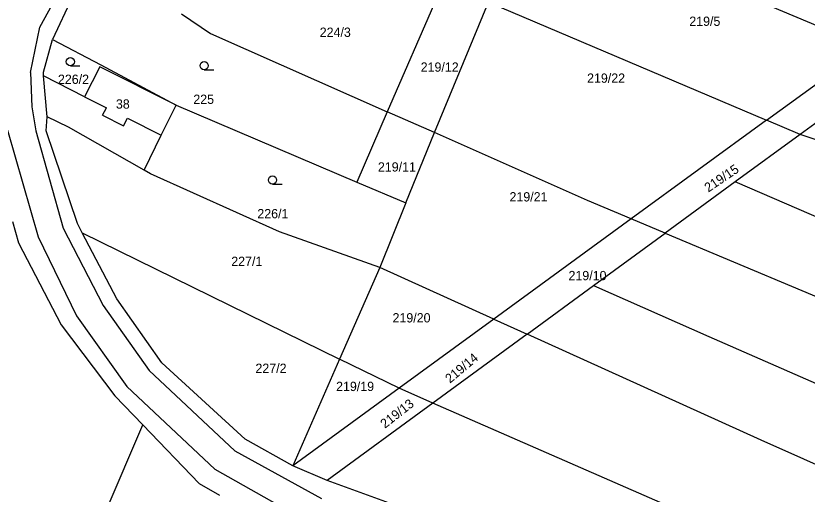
# Model space of a CAD drawing. Extents: x -744566 to -741843, y -1128407 to -1126744.
# Drawn here: x -743048.6 to -742903.8, y -1127789.3 to -1127701.7 of the extents above; entities that cross this region are included whole.
import ezdxf

# ---------------------------------------------------------------- set-up
doc = ezdxf.new("R2010")
doc.units = 0
for name, color, linetype in [('Hranice parcel', 7, 'Continuous'), ('Parcelní čísla', 7, 'Continuous'), ('Vnitřní kresba', 7, 'Continuous'), ('Značky kultur', 7, 'Continuous')]:
    doc.layers.add(name, color=color, linetype=linetype)

msp = doc.modelspace()

# ---------------------------------------------------------------- linework, layer by layer
at = {"layer": 'Hranice parcel'}
for p, q in [((-743035.1, -1127691.53), (-743041.92, -1127706.05)), ((-742970.18, -1127695.1), (-742980.63, -1127719.3)), ((-742972.01, -1127723.11), (-742962.09, -1127699.23)), ((-742962.09, -1127699.23), (-742911.19, -1127720.85)), ((-742911.19, -1127720.85), (-742892.82, -1127707.45)), ((-742886.72, -1127710.02), (-742905.07, -1127723.45)), ((-743042.89, -1127720.23), (-743043.57, -1127712.76)), ((-743019.3, -1127718.08), (-742986.19, -1127732.18)), ((-742980.63, -1127719.3), (-742986.19, -1127732.18)), ((-742972.01, -1127723.11), (-742980.63, -1127719.3)), ((-742911.19, -1127720.85), (-742935.96, -1127738.92)), ((-742905.07, -1127723.45), (-742911.19, -1127720.85)), ((-742977.22, -1127736), (-742972.01, -1127723.11)), ((-742905.07, -1127723.45), (-742916.95, -1127732.14)), ((-742986.19, -1127732.18), (-742977.22, -1127736)), ((-742916.95, -1127732.14), (-742929.76, -1127741.52)), ((-742977.22, -1127736), (-742982, -1127747.83)), ((-742935.96, -1127738.92), (-742961.12, -1127757.28)), ((-742929.76, -1127741.52), (-742935.96, -1127738.92)), ((-743036.47, -1127741.45), (-742989.35, -1127764.58)), ((-742942.9, -1127751.14), (-742929.76, -1127741.52)), ((-742982, -1127747.83), (-742989.35, -1127764.58)), ((-742961.12, -1127757.28), (-742982, -1127747.83)), ((-742955.04, -1127760.03), (-742942.9, -1127751.14)), ((-742961.12, -1127757.28), (-742978.46, -1127769.93)), ((-742961.12, -1127757.28), (-742955.04, -1127760.03)), ((-742955.04, -1127760.03), (-742972.27, -1127772.64)), ((-742989.35, -1127764.58), (-742997.92, -1127784.13)), ((-742978.46, -1127769.93), (-742989.35, -1127764.58)), ((-742978.46, -1127769.93), (-742997.92, -1127784.13)), ((-742972.27, -1127772.64), (-742978.46, -1127769.93)), ((-742972.27, -1127772.64), (-742991.64, -1127786.82)), ((-742833.19, -1127833.4), (-742972.27, -1127772.64)), ((-742991.64, -1127786.82), (-742997.92, -1127784.13))]:
    msp.add_line(p, q, dxfattribs=at)
for points in [[(-742892.82, -1127707.45), (-742959.07, -1127679.57), (-742986.2, -1127666.67), (-743003.07, -1127657.38)], [(-743018.27, -1127701.4), (-743013, -1127704.97), (-742980.63, -1127719.3)], [(-743043.57, -1127712.76), (-743043.55, -1127712.08), (-743041.92, -1127706.05)], [(-743041.92, -1127706.05), (-743033.05, -1127710.69), (-743019.3, -1127718.08)], [(-743019.3, -1127718.08), (-743033.26, -1127711.09), (-743036.05, -1127716.56), (-743043.57, -1127712.76)], [(-743025.14, -1127730.02), (-743022, -1127723.61), (-743019.3, -1127718.08)], [(-743036.47, -1127741.45), (-743037.36, -1127739.74), (-743043.04, -1127722.81), (-743042.89, -1127720.23)], [(-743025.14, -1127730.02), (-743039.01, -1127722.1), (-743042.89, -1127720.23)], [(-742935.96, -1127738.92), (-742943.98, -1127735.55), (-742972.01, -1127723.11)], [(-742697.57, -1127810.08), (-742723.74, -1127797.75), (-742779.52, -1127774.85), (-742849.36, -1127744.61), (-742849.6, -1127747), (-742896.29, -1127726.42), (-742905.07, -1127723.45)], [(-742982, -1127747.83), (-743000.34, -1127741.31), (-743023.98, -1127730.68), (-743025.14, -1127730.02)], [(-742705.33, -1127822.31), (-742752.11, -1127800.85), (-742855.88, -1127756.96), (-742856.57, -1127758.28), (-742916.95, -1127732.14)], [(-743049.21, -1127739.41), (-743048.14, -1127743.3), (-743040.35, -1127758.3), (-743030.5, -1127771.33), (-743025.38, -1127776.65)], [(-742997.92, -1127784.13), (-743006.65, -1127779.24), (-743021.89, -1127765.25), (-743030.16, -1127753.57), (-743036.47, -1127741.45)], [(-742929.76, -1127741.52), (-742892.25, -1127757.26), (-742839.56, -1127779.37), (-742839.56, -1127777.92), (-742777.16, -1127805.95), (-742712.92, -1127837.01)], [(-742942.9, -1127751.14), (-742921.78, -1127760.46), (-742847.12, -1127793.15), (-742812.02, -1127809), (-742724.3, -1127849.19), (-742701.43, -1127856.81), (-742666.84, -1127871.89)], [(-742670.28, -1127883.77), (-742733.59, -1127858.01), (-742796.71, -1127830.89), (-742912.22, -1127779.41), (-742955.04, -1127760.03)], [(-743103, -1128100.87), (-743064.96, -1127935.44), (-743045.29, -1127844.24), (-743032.09, -1127792.31), (-743025.38, -1127776.65)], [(-743025.38, -1127776.65), (-743015.05, -1127787.39), (-743011.33, -1127789.48)], [(-742830.43, -1127861.03), (-742831.55, -1127859.78), (-742848.33, -1127844.01), (-742864.61, -1127832.85), (-742882.56, -1127824.07), (-742889.66, -1127821.18), (-742902.77, -1127815.89), (-742967.48, -1127795.61), (-742991.64, -1127786.82)]]:
    msp.add_lwpolyline(points, dxfattribs=at)
at = {"layer": 'Vnitřní kresba'}
for p, q in [((-743044.25, -1127703.82), (-743036.85, -1127690.37)), ((-743045.96, -1127712.14), (-743044.25, -1127703.82)), ((-743045.96, -1127712.14), (-743045.67, -1127718.43)), ((-743036.05, -1127716.56), (-743032.05, -1127718.56)), ((-743045.67, -1127718.43), (-743044.96, -1127722.78)), ((-743032.75, -1127719.95), (-743032.05, -1127718.56)), ((-743032.75, -1127719.95), (-743028.9, -1127721.9)), ((-743028.9, -1127721.9), (-743028.19, -1127720.5)), ((-743028.19, -1127720.5), (-743022, -1127723.61)), ((-743050.12, -1127722.67), (-743044.56, -1127742.19)), ((-743044.96, -1127722.78), (-743039.98, -1127740.62)), ((-743039.98, -1127740.62), (-743032.62, -1127754.77)), ((-743044.56, -1127742.19), (-743037.53, -1127756.7)), ((-743032.62, -1127754.77), (-743024.19, -1127766.7)), ((-743037.53, -1127756.7), (-743028.31, -1127769.6)), ((-743024.19, -1127766.7), (-743008.52, -1127781.37)), ((-743028.31, -1127769.6), (-743012.17, -1127784.72)), ((-743008.52, -1127781.37), (-742992.69, -1127790.12)), ((-743012.17, -1127784.72), (-742994.83, -1127794.53))]:
    msp.add_line(p, q, dxfattribs=at)
at = {"layer": 'Značky kultur'}
for p, q in [((-743038.643, -1127710.9), (-743036.893, -1127710.9)), ((-743014.153, -1127711.62), (-743012.403, -1127711.62)), ((-743001.633, -1127732.56), (-742999.883, -1127732.56))]:
    msp.add_line(p, q, dxfattribs=at)
for centre in [(-743038.643, -1127710.15), (-743014.153, -1127710.87), (-743001.633, -1127731.81)]:
    msp.add_circle(centre, 0.75, dxfattribs=at)

# ---------------------------------------------------------------- texts
at = {"layer": 'Parcelní čísla'}
for s, p in [('219/5', (-742925.35, -1127703.59)), ('224/3', (-742992.993, -1127705.6)), ('219/12', (-742974.515, -1127711.98)), ('226/2', (-743040.913, -1127714.21)), ('219/22', (-742944.06, -1127714)), ('225', (-743016.134, -1127717.87)), ('38', (-743030.302, -1127718.74)), ('219/11', (-742982.345, -1127730.26)), ('219/21', (-742958.26, -1127735.73)), ('226/1', (-743004.413, -1127738.81)), ('227/1', (-743009.19, -1127747.54)), ('219/10', (-742947.46, -1127750.15)), ('219/20', (-742979.67, -1127757.88)), ('227/2', (-743004.76, -1127767.12)), ('219/19', (-742990, -1127770.44))]:
    msp.add_text(s, height=1.7, dxfattribs=at).set_placement(p)
for s, rotation, p in [('219/15', 34, (-742921.864, -1127734.114)), ('219/14', 40, (-742969.153, -1127769.101)), ('219/13', 38, (-742981.066, -1127777.359))]:
    msp.add_text(s, height=1.7, rotation=rotation, dxfattribs=at).set_placement(p)

doc.saveas('drawing.dxf')
